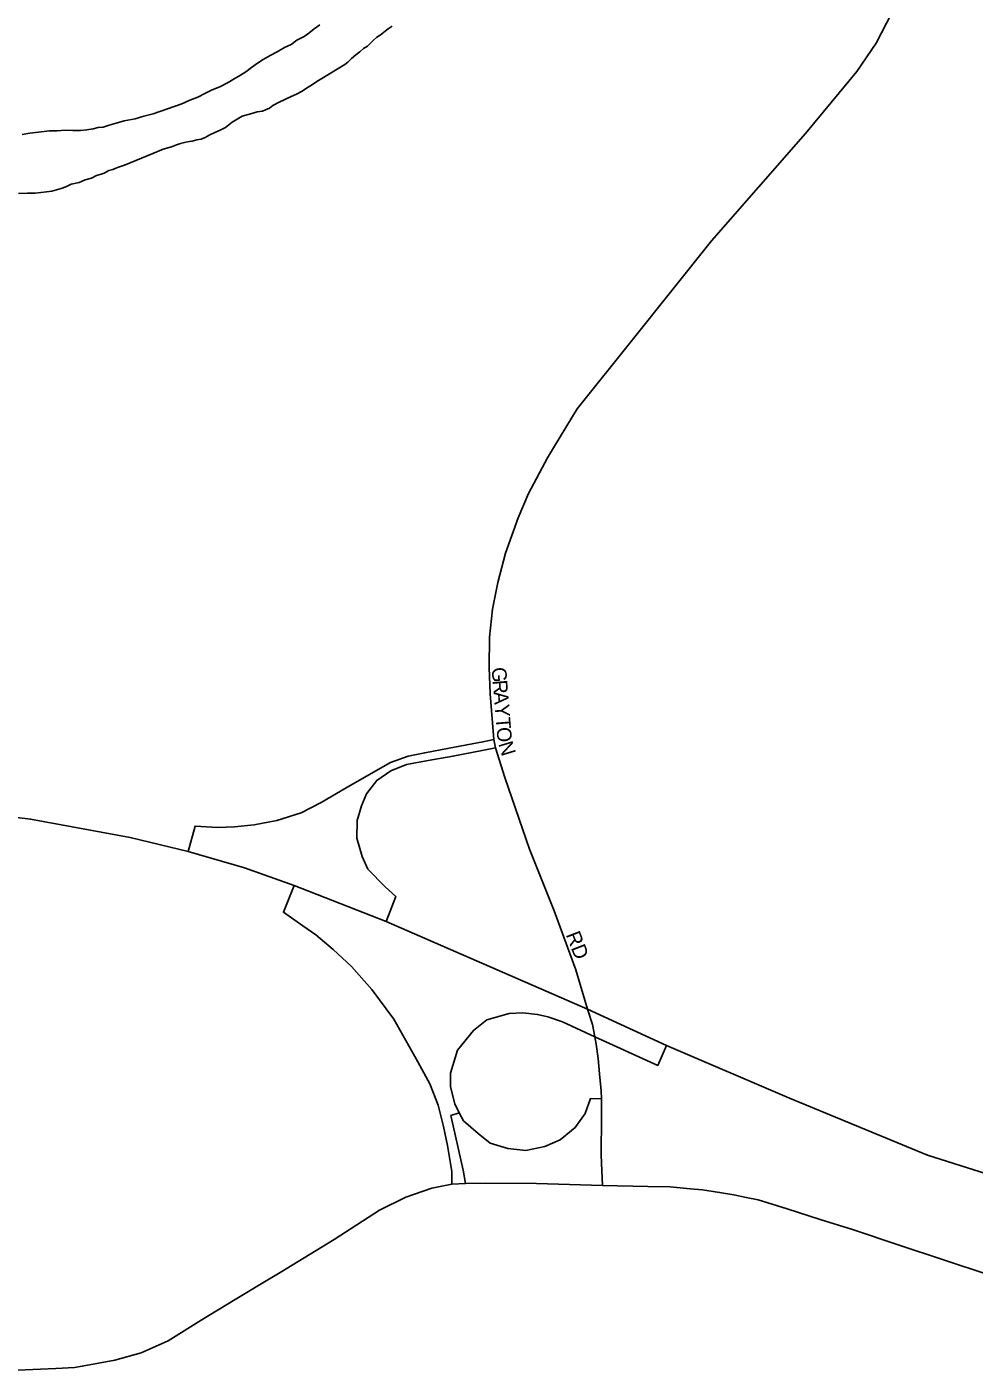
# Model space of a CAD drawing. Extents: x -561 to 1170, y 0 to 846.
# Drawn here: x 126.99 to 135.77, y 208.55 to 221.02 of the extents above; entities that cross this region are included whole.
import ezdxf

# ---------------------------------------------------------------- set-up
doc = ezdxf.new("R2010")
doc.units = 0
for name, color, linetype in [('GM_X_City_Street', 7, 'Continuous'), ('GM_X_City_Street_Text', 7, 'Continuous'), ('GM_X_Interchange_Ramps', 7, 'Continuous'), ('GM_X_Interstate_Route', 7, 'Continuous'), ('GM_X_Major_River', 7, 'Continuous'), ('GM_X_State_Route', 7, 'Continuous')]:
    doc.layers.add(name, color=color, linetype=linetype)

msp = doc.modelspace()

# ---------------------------------------------------------------- linework, layer by layer
at = {"layer": 'GM_X_City_Street'}
for points in [[(131.882, 217.13), (132.092, 217.476), (132.6, 218.111), (133.337, 219.033), (134.208, 220.03), (134.687, 220.603), (134.865, 220.867), (135.011, 221.149), (135.119, 221.441), (135.208, 221.749), (135.372, 222.63), (135.603, 223.932)], [(132.299, 211.307), (132.285, 211.45), (132.267, 211.581), (132.254, 211.651), (132.233, 211.763), (132.188, 211.906), (132.078, 212.271), (131.877, 212.818), (131.65, 213.391), (131.42, 214.055), (131.333, 214.33), (131.317, 214.408), (131.283, 214.832), (131.275, 215.077), (131.279, 215.356), (131.306, 215.616), (131.356, 215.864), (131.425, 216.136), (131.544, 216.463), (131.64, 216.691), (131.816, 217.021), (131.882, 217.13)], [(132.326, 210.27), (132.317, 210.479), (132.313, 210.557), (132.317, 210.906), (132.316, 211.076), (132.315, 211.149), (132.299, 211.307)]]:
    msp.add_lwpolyline(points, dxfattribs=at)
at = {"layer": 'GM_X_Interchange_Ramps'}
for points in [[(131.317, 214.408), (131.217, 214.385), (130.902, 214.327), (130.677, 214.285), (130.524, 214.253), (130.358, 214.194), (130.157, 214.08), (129.948, 213.958), (129.717, 213.823), (129.53, 213.729), (129.306, 213.658), (129.094, 213.617), (128.911, 213.599), (128.758, 213.593), (128.652, 213.599), (128.546, 213.605), (128.481, 213.369)], [(130.319, 212.721), (130.408, 212.951), (130.31, 213.041), (130.148, 213.204), (130.096, 213.322), (130.048, 213.493), (130.049, 213.656), (130.09, 213.793), (130.137, 213.905), (130.231, 214.029), (130.361, 214.117), (130.509, 214.176), (130.708, 214.212), (130.938, 214.253), (131.209, 214.306), (131.333, 214.33)], [(129.464, 213.053), (129.366, 212.806), (129.546, 212.68), (129.665, 212.597), (129.827, 212.459), (129.998, 212.302), (130.187, 212.088), (130.389, 211.813), (130.614, 211.418), (130.723, 211.215), (130.8, 211.016), (130.851, 210.819), (130.888, 210.643), (130.929, 210.4), (130.927, 210.284)], [(132.316, 211.076), (132.214, 211.077), (132.164, 210.939), (132.071, 210.809), (131.934, 210.696), (131.79, 210.634), (131.616, 210.597), (131.447, 210.615), (131.285, 210.665), (131.173, 210.752), (131.036, 210.871), (130.997, 210.946), (130.955, 211.027), (130.915, 211.187), (130.917, 211.314), (130.98, 211.526), (131.129, 211.71), (131.254, 211.806), (131.461, 211.865), (131.588, 211.873), (131.723, 211.858), (131.818, 211.836), (131.954, 211.788), (132.254, 211.651), (132.839, 211.385), (132.921, 211.57)], [(131.056, 210.289), (131.033, 210.413), (130.919, 210.92), (130.997, 210.946)]]:
    msp.add_lwpolyline(points, dxfattribs=at)
at = {"layer": 'GM_X_Interstate_Route'}
for points in [[(125.396, 213.844), (126.072, 213.782), (127.02, 213.67), (127.943, 213.499), (128.481, 213.369), (129.006, 213.216), (129.464, 213.053), (130.319, 212.721), (132.188, 211.906)], [(132.188, 211.906), (132.921, 211.57), (134.06, 211.08), (135.341, 210.553), (136.318, 210.242), (137.354, 210.023)]]:
    msp.add_lwpolyline(points, dxfattribs=at)
at = {"layer": 'GM_X_Major_River'}
for points in [[(126.909, 219.472), (126.991, 219.474), (127.061, 219.475), (127.115, 219.482), (127.169, 219.488), (127.218, 219.495), (127.261, 219.506), (127.304, 219.518), (127.347, 219.535), (127.395, 219.558), (127.471, 219.575), (127.525, 219.598), (127.584, 219.615), (127.632, 219.638), (127.675, 219.65), (127.702, 219.661), (127.745, 219.684), (127.783, 219.695), (127.826, 219.712), (127.891, 219.735), (128.154, 219.843), (128.251, 219.883), (128.326, 219.906), (128.375, 219.923), (128.412, 219.935), (128.461, 219.947), (128.493, 219.953), (128.52, 219.959), (128.563, 219.97), (128.601, 219.976), (128.639, 219.993), (128.682, 220.016), (128.73, 220.038), (128.778, 220.061), (128.827, 220.084), (128.891, 220.134), (128.982, 220.19), (129.074, 220.213), (129.122, 220.23), (129.171, 220.237), (129.198, 220.248), (129.235, 220.265), (129.267, 220.287), (129.321, 220.315), (129.38, 220.343), (129.439, 220.372), (129.487, 220.394), (129.541, 220.422), (129.579, 220.45), (129.627, 220.478), (129.675, 220.512), (129.723, 220.54), (129.777, 220.573), (129.937, 220.668), (129.964, 220.691), (129.996, 220.724), (130.039, 220.757), (130.076, 220.785), (130.108, 220.818), (130.146, 220.84), (130.172, 220.863), (130.199, 220.89), (130.231, 220.923), (130.263, 220.94), (130.311, 220.979), (130.338, 221.001), (130.375, 221.024)], [(126.909, 219.472), (126.991, 219.474), (127.061, 219.475), (127.115, 219.482), (127.169, 219.488), (127.218, 219.495), (127.261, 219.506), (127.304, 219.518), (127.347, 219.535), (127.395, 219.558), (127.471, 219.575), (127.525, 219.598), (127.584, 219.615), (127.632, 219.638), (127.675, 219.65), (127.702, 219.661), (127.745, 219.684), (127.783, 219.695), (127.826, 219.712), (127.891, 219.735), (128.154, 219.843), (128.251, 219.883), (128.326, 219.906), (128.375, 219.923), (128.412, 219.935), (128.461, 219.947), (128.493, 219.953), (128.52, 219.959), (128.563, 219.97), (128.601, 219.976), (128.639, 219.993), (128.682, 220.016), (128.73, 220.038), (128.778, 220.061), (128.827, 220.084), (128.891, 220.134), (128.982, 220.19), (129.074, 220.213), (129.122, 220.23), (129.171, 220.237), (129.198, 220.248), (129.235, 220.265), (129.267, 220.287), (129.321, 220.315), (129.38, 220.343), (129.439, 220.372), (129.487, 220.394), (129.541, 220.422), (129.579, 220.45), (129.627, 220.478), (129.675, 220.512), (129.723, 220.54), (129.777, 220.573), (129.937, 220.668), (129.964, 220.691), (129.996, 220.724), (130.039, 220.757), (130.076, 220.785), (130.108, 220.818), (130.146, 220.84), (130.172, 220.863), (130.199, 220.89), (130.231, 220.923), (130.263, 220.94), (130.311, 220.979), (130.338, 221.001), (130.375, 221.024)], [(126.942, 220.02), (127.013, 220.033), (127.094, 220.04), (127.196, 220.052), (127.267, 220.054), (127.343, 220.061), (127.413, 220.057), (127.484, 220.058), (127.543, 220.064), (127.602, 220.071), (127.646, 220.083), (127.694, 220.089), (127.748, 220.106), (127.813, 220.124), (127.888, 220.147), (127.991, 220.165), (128.072, 220.188), (128.158, 220.212), (128.422, 220.303), (128.497, 220.337), (128.572, 220.366), (128.637, 220.4), (128.706, 220.434), (128.776, 220.462), (128.852, 220.501), (128.91, 220.535), (128.969, 220.569), (129.018, 220.602), (129.071, 220.641), (129.125, 220.68), (129.178, 220.714), (129.242, 220.753), (129.307, 220.786), (129.376, 220.826), (129.436, 220.854), (129.489, 220.893), (129.559, 220.927), (129.602, 220.96), (129.65, 220.999), (129.703, 221.038)], [(129.703, 221.038), (129.65, 220.999), (129.602, 220.96), (129.559, 220.927), (129.489, 220.893), (129.436, 220.854), (129.376, 220.826), (129.307, 220.786), (129.242, 220.753), (129.178, 220.714), (129.125, 220.68), (129.071, 220.641), (129.018, 220.602), (128.969, 220.569), (128.91, 220.535), (128.852, 220.501), (128.776, 220.462), (128.706, 220.434), (128.637, 220.4), (128.572, 220.366), (128.497, 220.337), (128.422, 220.303), (128.158, 220.212), (128.072, 220.188), (127.991, 220.165), (127.888, 220.147), (127.813, 220.124), (127.748, 220.106), (127.694, 220.089), (127.646, 220.083), (127.602, 220.071), (127.543, 220.064), (127.484, 220.058), (127.413, 220.057), (127.343, 220.061), (127.267, 220.054), (127.196, 220.052), (127.094, 220.04), (127.013, 220.033), (126.942, 220.02)]]:
    msp.add_lwpolyline(points, dxfattribs=at)
at = {"layer": 'GM_X_State_Route'}
for points in [[(129.174, 209.368), (129.335, 209.464), (129.837, 209.771), (130.256, 210.041), (130.5, 210.162), (130.744, 210.246), (130.927, 210.284), (131.056, 210.289), (131.243, 210.292), (131.715, 210.289), (132.326, 210.27)], [(132.326, 210.27), (132.748, 210.262), (132.953, 210.258), (133.138, 210.241), (133.253, 210.231), (133.412, 210.207), (133.544, 210.184), (133.66, 210.161), (133.771, 210.137), (134.039, 210.055), (134.346, 209.957), (134.644, 209.863), (135.079, 209.717), (136.312, 209.31), (137.411, 208.962), (137.849, 208.815), (138.164, 208.727), (138.443, 208.666), (138.674, 208.633), (139.109, 208.612), (139.854, 208.615)], [(123.815, 208.559), (124.742, 208.549), (126.083, 208.565), (126.757, 208.551), (127.253, 208.575), (127.427, 208.582), (127.499, 208.595), (127.802, 208.65), (128.045, 208.719), (128.297, 208.83), (128.604, 209.022), (128.917, 209.214), (129.174, 209.368)]]:
    msp.add_lwpolyline(points, dxfattribs=at)

# ---------------------------------------------------------------- texts
at = {"layer": 'GM_X_City_Street_Text'}
for s, rotation, p in [('G', 274.7038, (131.297, 215.073)), ('R', 274.6931, (131.306, 214.955)), ('A', 274.6898, (131.315, 214.848)), ('Y', 274.682, (131.325, 214.73)), ('T', 274.6941, (131.334, 214.611)), ('O', 274.6898, (131.342, 214.517)), ('N', 286.8819, (131.358, 214.368)), ('RD', 291.2488, (131.984, 212.598))]:
    msp.add_text(s, height=0.135, rotation=rotation, dxfattribs=at).set_placement(p)

doc.saveas('drawing.dxf')
